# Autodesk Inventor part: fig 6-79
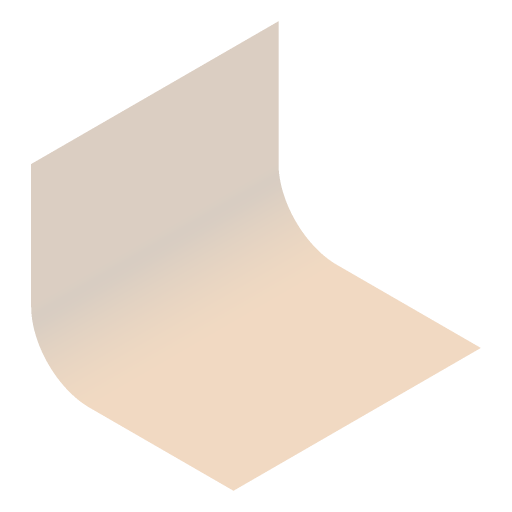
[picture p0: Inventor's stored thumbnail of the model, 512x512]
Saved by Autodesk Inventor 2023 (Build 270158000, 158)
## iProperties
Part Number: fig 6-79
Document SubType Name: Modeling
Created: 2003-10
Designer: Owner
Manufacturer: Standard
Standards Organization: Custom
Density: 1 g/cm^3
Material: Generic
Appearance: Default
Control State: 0
Master: False
Checked Out: False
Shininess: 64.0
Length Units: 11269
Angle Units: 11279
Time Units: 11290
Mass Units: 11283
Length Display Precision: 3
Angle Display Precision: 2
Compacted: True
Density: 0.0
Volumn: 0.0
Area: 0.0
PropertySet Name: Model Information
Author: Owner
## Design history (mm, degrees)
node "Sketch1"
sketch "Sketch2"
  geometry: L1 (22.777, 31.862)-(22.777, 0.2); L2 (7.777, -14.8)-(-29.161, -14.8); A1 r 15 centre (7.777, 0.2) between (7.777, -14.8) and (22.777, 0.2)
  constraints: 4 end point, 2 point on circle, 2 tangent, 1 centre point, 1 perpendicular, 1 vertical
  dimensions: "d23" = 15 radius of A1
extrude_surface "ExtrusionSrf1" sketch "Sketch2" dims "d24" = 63.5, "d25" = 0
body "Srf1"
